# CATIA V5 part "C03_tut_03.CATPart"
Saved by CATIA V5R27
Part number: Part1
Bounding box of the stored display mesh (mm): x 0 to 0, y -100 to 100, z 0 to 90
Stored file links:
  E:\_Deepak\2017_Deepak\CATIA\Resources\Tutorial Files\Tutorials\c03_catia_v5_6r2016_tut\C03_tut_03.CATPart
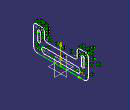
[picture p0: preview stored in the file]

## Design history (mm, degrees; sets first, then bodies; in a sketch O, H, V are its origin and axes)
Body1 (main body)
  Sketch1 on yz-plane, origin (0, 0, 0), H (0, 1, 0), V (0, 0, 1)
    line L1 (0, 0) -> (85, 0)
    line L2 (100, 15) -> (100, 80)
    line L3 (90, 90) -> (70, 90)
    line L4 (60, 80) -> (60, 60)
    line L5 (50, 50) -> (0, 50)
    point P1 (0, 50)
    arc A1 centre (90, 80) radius 10 from (90, 90) to (100, 80) cw
    point P2 (90, 90)
    point P3 (100, 80)
    point P4 (90, 80)
    arc A2 centre (85, 15) radius 15 from (85, 0) to (100, 15) ccw
    point P5 (85, 0)
    point P6 (100, 15)
    arc A3 centre (50, 60) radius 10 from (50, 50) to (60, 60) ccw
    point P8 (50, 50)
    point P9 (60, 60)
    construction line L6 (80, 40) -> (80, 70)
    line L7 (75, 40) -> (75, 70)
    line L8 (85, 70) -> (85, 40)
    arc A4 centre (80, 70) radius 5 from (75, 70) to (85, 70) cw
    arc A5 centre (80, 40) radius 5 from (85, 40) to (75, 40) cw
    point P13 (75, 40)
    point P14 (75, 70)
    point P15 (85, 70)
    point P16 (85, 40)
    arc A6 centre (70, 80) radius 10 from (60, 80) to (70, 90) cw
    point P17 (60, 80)
    point P18 (70, 90)
    point P20 (0, 50)
    point P21 (-50, 50)
    line L9 (-50, 50) -> (0, 50)
    point P22 (-60, 60)
    arc A7 centre (-50, 60) radius 10 from (-50, 50) to (-60, 60) cw
    point P24 (-60, 80)
    line L10 (-60, 80) -> (-60, 60)
    point P25 (-70, 90)
    arc A8 centre (-70, 80) radius 10 from (-60, 80) to (-70, 90) ccw
    point P27 (-90, 90)
    line L11 (-90, 90) -> (-70, 90)
    point P28 (-100, 80)
    arc A9 centre (-90, 80) radius 10 from (-90, 90) to (-100, 80) ccw
    point P30 (-100, 15)
    line L12 (-100, 15) -> (-100, 80)
    point P31 (-85, 0)
    arc A10 centre (-85, 15) radius 15 from (-85, 0) to (-100, 15) cw
    point P33 (0, 0)
    line L13 (0, 0) -> (-85, 0)
    point P34 (-90, 80)
    construction line L14 (-80, 40) -> (-80, 70)
    point P37 (-75, 40)
    point P38 (-75, 70)
    point P39 (-85, 70)
    point P40 (-85, 40)
    line L15 (-75, 40) -> (-75, 70)
    line L16 (-85, 70) -> (-85, 40)
    arc A11 centre (-80, 70) radius 5 from (-75, 70) to (-85, 70) ccw
    arc A12 centre (-80, 40) radius 5 from (-85, 40) to (-75, 40) ccw
    construction line L17 (-60, 20) -> (60, 20)
    point P41 (-60, 20)
    line L18 (-60, 30) -> (60, 30)
    line L19 (60, 10) -> (-60, 10)
    arc A13 centre (60, 20) radius 10 from (60, 30) to (60, 10) cw
    arc A14 centre (-60, 20) radius 10 from (-60, 10) to (-60, 30) cw
    radius A1 = 10
    radius A2 = 15
    radius A3 = 10
    distance L6 L7 = 5
    radius A6 = 10
    horizontal: L1 H, L3 H, L5 H, L17 H
    vertical: L2 V, L4 V, L6 V
    tangency: A1 L3, A1 L2, A2 L1, A2 L2, A3 L5, A3 L4, A4 L7, A5 L7, A4 L8, A5 L8, A6 L4, A6 L3, A13 L18, A14 L18, A13 L19, A14 L19
    symmetry: P1 P20 V, P8 P21 V, L5 L9 V, P9 P22 V, A3 A7 V, P17 P24 V, L4 L10 V, P18 P25 V, A6 A8 V, P2 P27 V, L3 L11 V, P3 P28 V, A1 A9 V, P6 P30 V, L2 L12 V, P5 P31 V, A2 A10 V, O P33 V, L1 L13 V, P4 P34 V, L6 L14 V, P13 P37 V, P14 P38 V, P15 P39 V, P16 P40 V, L7 L15 V, L8 L16 V, A4 A11 V, A5 A12 V
    coincidence: P41 L10
    parallelism: L18 L17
